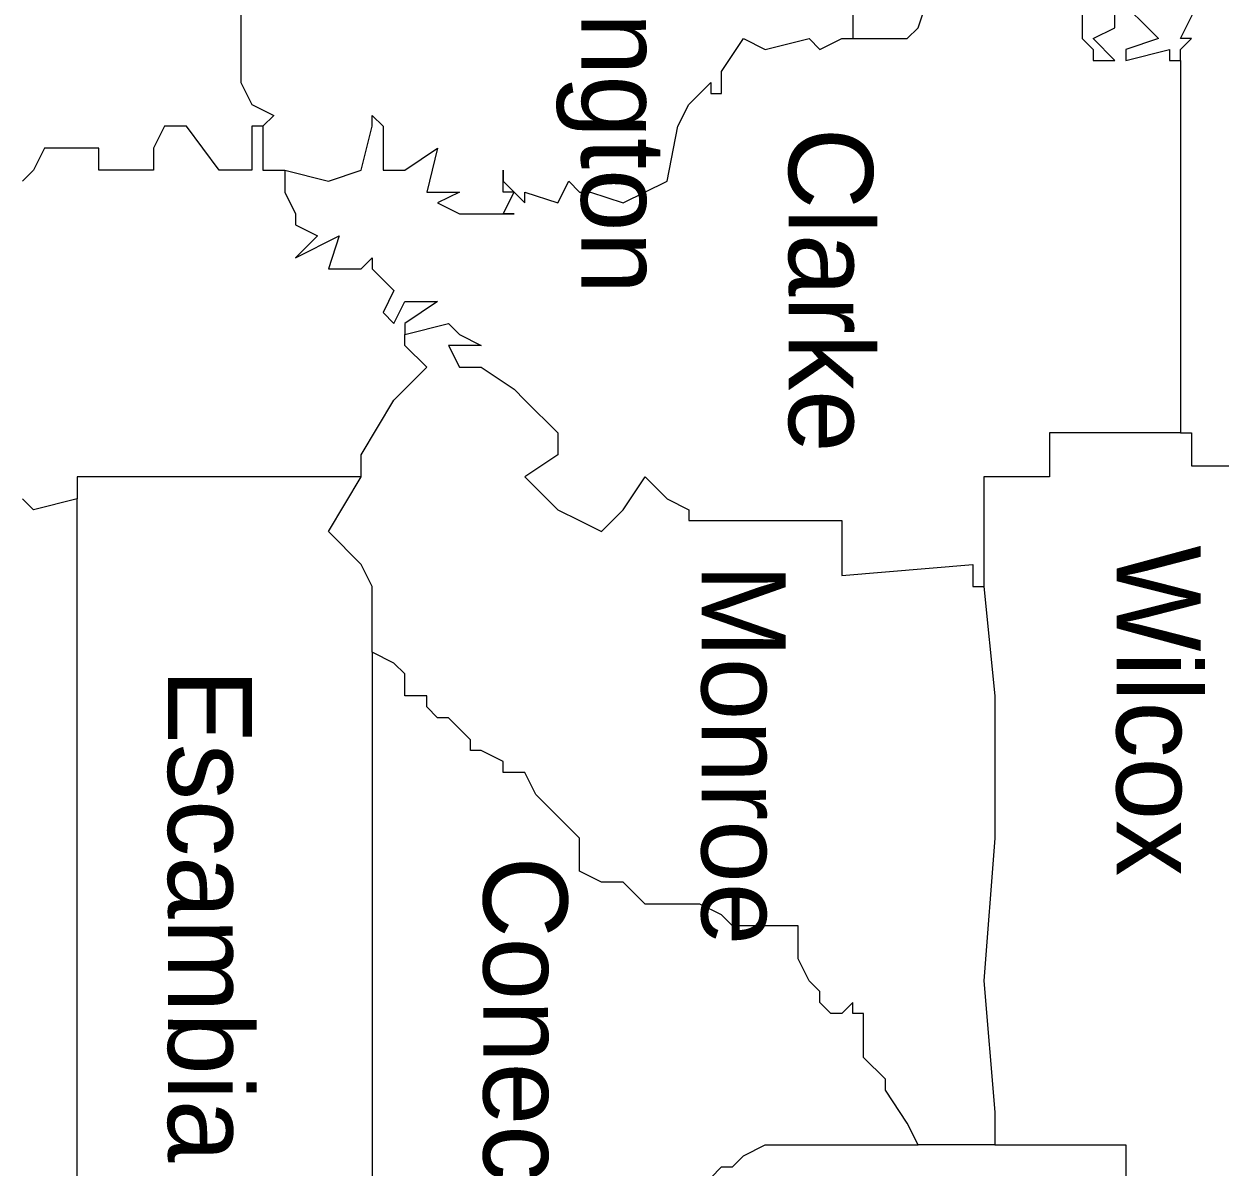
# Model space of a CAD drawing. Extents: x 0 to 0.917, y 0 to 0.708.
# Drawn here: x 0.3538 to 0.4279, y 0.5421 to 0.6129 of the extents above; entities that cross this region are included whole.
import ezdxf

# ---------------------------------------------------------------- set-up
doc = ezdxf.new("R2010")
doc.units = 0
doc.layers.add('ANNO-SHT', color=7, linetype='Continuous')
doc.layers.add('ANNO-TXT', color=7, linetype='Continuous')

msp = doc.modelspace()

# ---------------------------------------------------------------- linework, layer by layer
at = {"layer": 'ANNO-SHT'}
msp.add_line((0.413951, 0.54347), (0.409214, 0.54347), dxfattribs=at)
for points in [[(0.365231, 0.63306), (0.365231, 0.626952), (0.367261, 0.626952), (0.367261, 0.62288), (0.367261, 0.609305), (0.367938, 0.607948), (0.369291, 0.607269), (0.368614, 0.60659), (0.368614, 0.603876), (0.369968, 0.603876)], [(0.365231, 0.63306), (0.365231, 0.626952), (0.367261, 0.626952), (0.367261, 0.62288), (0.367261, 0.609305), (0.367938, 0.607948), (0.369291, 0.607269), (0.368614, 0.60659), (0.368614, 0.603876), (0.369968, 0.603876)], [(0.405154, 0.624916), (0.405154, 0.61202), (0.405831, 0.61202), (0.408537, 0.61202), (0.409214, 0.612699), (0.409891, 0.614735)], [(0.419364, 0.614735), (0.419364, 0.61202), (0.420041, 0.611341), (0.420041, 0.610663), (0.421394, 0.610663), (0.420041, 0.61202), (0.421394, 0.612699), (0.421394, 0.614735)], [(0.421394, 0.614735), (0.424101, 0.61202), (0.422071, 0.611341), (0.422071, 0.610663), (0.424777, 0.611341), (0.424777, 0.610663), (0.425454, 0.610663), (0.425454, 0.611341), (0.426131, 0.61202), (0.425454, 0.61202), (0.426807, 0.614735)], [(0.369968, 0.603876), (0.372674, 0.603197), (0.374704, 0.603876), (0.375381, 0.60659), (0.375381, 0.607269), (0.376058, 0.60659), (0.376058, 0.603876), (0.376734, 0.603876), (0.377411, 0.603876), (0.379441, 0.605233), (0.378764, 0.602518), (0.380794, 0.602518), (0.379441, 0.601839), (0.380794, 0.601161), (0.382148, 0.601161), (0.383501, 0.601161), (0.384178, 0.601161), (0.384178, 0.601161), (0.383501, 0.601161), (0.384178, 0.602518), (0.383501, 0.602518), (0.383501, 0.602518), (0.383501, 0.603876), (0.383501, 0.603197), (0.384178, 0.602518), (0.384854, 0.601839), (0.384854, 0.602518), (0.386884, 0.601839), (0.387561, 0.603197), (0.388238, 0.602518), (0.388914, 0.602518), (0.390944, 0.601839), (0.393651, 0.603197), (0.394328, 0.60659), (0.395004, 0.607948), (0.396358, 0.609305), (0.396358, 0.608627), (0.397034, 0.608627), (0.397034, 0.609984), (0.398388, 0.61202), (0.399741, 0.611341), (0.402448, 0.61202), (0.403124, 0.611341), (0.404478, 0.61202), (0.405154, 0.61202)], [(0.425454, 0.610663), (0.425454, 0.607269), (0.425454, 0.593016), (0.425454, 0.587586), (0.426131, 0.587586), (0.426131, 0.586908), (0.426131, 0.58555), (0.426807, 0.58555), (0.434927, 0.58555), (0.434927, 0.581478), (0.434927, 0.579442), (0.435604, 0.579442), (0.441017, 0.579442), (0.442371, 0.579442), (0.443047, 0.579442), (0.443724, 0.578763), (0.443724, 0.578084), (0.443724, 0.578084), (0.443724, 0.577406), (0.443724, 0.576727), (0.443724, 0.576727)], [(0.368614, 0.60659), (0.367938, 0.60659), (0.367938, 0.605233), (0.367938, 0.603876), (0.367261, 0.603876), (0.365908, 0.603876), (0.363878, 0.60659), (0.363878, 0.60659), (0.362524, 0.60659), (0.361848, 0.605233), (0.361848, 0.603876), (0.361848, 0.603876), (0.360495, 0.603876), (0.359818, 0.603876), (0.359818, 0.603876), (0.359141, 0.603876), (0.358465, 0.603876), (0.358465, 0.605233), (0.358465, 0.605233), (0.357111, 0.605233), (0.355758, 0.605233), (0.355081, 0.605233), (0.355081, 0.605233), (0.355081, 0.605233), (0.354405, 0.603876), (0.354405, 0.603876), (0.353728, 0.603197)], [(0.369968, 0.603876), (0.369968, 0.602518), (0.370644, 0.601161), (0.370644, 0.600482), (0.371998, 0.599803), (0.370644, 0.598446), (0.373351, 0.599803), (0.372674, 0.597767), (0.373351, 0.597767), (0.374704, 0.597767), (0.375381, 0.598446), (0.375381, 0.597767), (0.376734, 0.59641), (0.376058, 0.595052), (0.376734, 0.594374), (0.377411, 0.595731), (0.379441, 0.595731), (0.377411, 0.594374), (0.377411, 0.593695)], [(0.369968, 0.603876), (0.369968, 0.602518), (0.370644, 0.601161), (0.370644, 0.600482), (0.371998, 0.599803), (0.370644, 0.598446), (0.373351, 0.599803), (0.372674, 0.597767), (0.373351, 0.597767), (0.374704, 0.597767), (0.375381, 0.598446), (0.375381, 0.597767), (0.376734, 0.59641), (0.376058, 0.595052), (0.376734, 0.594374), (0.377411, 0.595731), (0.379441, 0.595731), (0.377411, 0.594374), (0.377411, 0.593695)], [(0.377411, 0.593695), (0.380118, 0.594374), (0.380794, 0.593695), (0.382148, 0.593016), (0.380118, 0.593016), (0.380794, 0.591659), (0.382148, 0.591659), (0.384178, 0.590301), (0.384854, 0.589622), (0.384854, 0.589622), (0.386884, 0.587586), (0.386884, 0.586229), (0.384854, 0.584871), (0.386884, 0.582835), (0.386884, 0.582835), (0.388238, 0.582157), (0.389591, 0.581478), (0.390944, 0.582835), (0.392298, 0.584871), (0.393651, 0.583514), (0.395004, 0.582835), (0.395004, 0.582157), (0.396358, 0.582157), (0.404478, 0.582157), (0.404478, 0.578763), (0.412597, 0.579442), (0.412597, 0.578084), (0.413274, 0.578084)], [(0.409214, 0.54347), (0.408537, 0.544827), (0.408537, 0.544827), (0.407184, 0.546863), (0.407184, 0.547542), (0.405831, 0.548899), (0.405831, 0.550257), (0.405831, 0.550936), (0.405831, 0.551614), (0.405831, 0.551614), (0.405154, 0.551614), (0.405154, 0.552293), (0.404478, 0.551614), (0.403801, 0.551614), (0.403801, 0.551614), (0.403124, 0.552293), (0.403124, 0.552972), (0.402448, 0.55365), (0.401771, 0.555008), (0.401771, 0.556365), (0.401771, 0.557044), (0.399741, 0.557044), (0.398388, 0.557044), (0.397711, 0.557044), (0.397034, 0.557723), (0.395681, 0.558401), (0.395004, 0.558401), (0.395004, 0.558401), (0.393651, 0.558401), (0.392298, 0.558401), (0.391621, 0.55908), (0.390944, 0.559759), (0.390944, 0.559759), (0.389591, 0.559759), (0.389591, 0.559759), (0.388238, 0.560438), (0.388238, 0.562474), (0.387561, 0.563152), (0.385531, 0.565189), (0.385531, 0.565189), (0.385531, 0.565189), (0.384854, 0.566546), (0.384178, 0.566546), (0.384178, 0.566546), (0.383501, 0.566546), (0.383501, 0.567225), (0.382148, 0.567904), (0.381471, 0.567904), (0.381471, 0.568582), (0.380118, 0.56994), (0.379441, 0.56994), (0.379441, 0.56994), (0.378764, 0.570618), (0.378764, 0.571297), (0.378764, 0.571297), (0.377411, 0.571297), (0.377411, 0.572655), (0.377411, 0.572655), (0.376734, 0.573333), (0.375381, 0.574012), (0.375381, 0.577406), (0.375381, 0.578084), (0.374704, 0.579442), (0.372674, 0.581478), (0.374704, 0.584871), (0.374704, 0.586229), (0.376734, 0.589622), (0.377411, 0.590301), (0.378764, 0.591659), (0.377411, 0.593016), (0.377411, 0.593695)], [(0.409214, 0.54347), (0.408537, 0.544827), (0.408537, 0.544827), (0.407184, 0.546863), (0.407184, 0.547542), (0.405831, 0.548899), (0.405831, 0.550257), (0.405831, 0.550936), (0.405831, 0.551614), (0.405831, 0.551614), (0.405154, 0.551614), (0.405154, 0.552293), (0.404478, 0.551614), (0.403801, 0.551614), (0.403801, 0.551614), (0.403124, 0.552293), (0.403124, 0.552972), (0.402448, 0.55365), (0.401771, 0.555008), (0.401771, 0.556365), (0.401771, 0.557044), (0.399741, 0.557044), (0.398388, 0.557044), (0.397711, 0.557044), (0.397034, 0.557723), (0.395681, 0.558401), (0.395004, 0.558401), (0.395004, 0.558401), (0.393651, 0.558401), (0.392298, 0.558401), (0.391621, 0.55908), (0.390944, 0.559759), (0.390944, 0.559759), (0.389591, 0.559759), (0.389591, 0.559759), (0.388238, 0.560438), (0.388238, 0.562474), (0.387561, 0.563152), (0.385531, 0.565189), (0.385531, 0.565189), (0.385531, 0.565189), (0.384854, 0.566546), (0.384178, 0.566546), (0.384178, 0.566546), (0.383501, 0.566546), (0.383501, 0.567225), (0.382148, 0.567904), (0.381471, 0.567904), (0.381471, 0.568582), (0.380118, 0.56994), (0.379441, 0.56994), (0.379441, 0.56994), (0.378764, 0.570618), (0.378764, 0.571297), (0.378764, 0.571297), (0.377411, 0.571297), (0.377411, 0.572655), (0.377411, 0.572655), (0.376734, 0.573333), (0.375381, 0.574012), (0.375381, 0.577406), (0.375381, 0.578084), (0.374704, 0.579442), (0.372674, 0.581478), (0.374704, 0.584871), (0.374704, 0.586229), (0.376734, 0.589622), (0.377411, 0.590301), (0.378764, 0.591659), (0.377411, 0.593016), (0.377411, 0.593695)], [(0.425454, 0.587586), (0.424101, 0.587586), (0.417334, 0.587586), (0.417334, 0.586229), (0.417334, 0.584871), (0.413274, 0.584871), (0.413274, 0.578084), (0.413951, 0.571297), (0.413951, 0.562474), (0.413274, 0.55365), (0.413951, 0.545506), (0.413951, 0.54347)], [(0.374704, 0.584871), (0.360495, 0.584871), (0.357111, 0.584871), (0.357111, 0.584871), (0.357111, 0.583514)], [(0.357111, 0.529895), (0.357111, 0.530574), (0.357111, 0.53261), (0.357111, 0.550936), (0.357111, 0.563831), (0.357111, 0.577406), (0.357111, 0.583514), (0.354405, 0.582835), (0.353728, 0.583514)], [(0.375381, 0.574012), (0.375381, 0.561795), (0.375381, 0.559759), (0.375381, 0.550936), (0.375381, 0.535325)], [(0.393651, 0.530574), (0.393651, 0.53261), (0.393651, 0.533968), (0.393651, 0.540076), (0.394328, 0.540076), (0.394328, 0.540755), (0.395004, 0.540755), (0.395681, 0.541434), (0.396358, 0.541434), (0.397034, 0.542112), (0.397711, 0.542112), (0.398388, 0.542791), (0.399741, 0.54347), (0.400418, 0.54347), (0.403801, 0.54347), (0.404478, 0.54347), (0.409214, 0.54347)], [(0.393651, 0.530574), (0.393651, 0.53261), (0.393651, 0.533968), (0.393651, 0.540076), (0.394328, 0.540076), (0.394328, 0.540755), (0.395004, 0.540755), (0.395681, 0.541434), (0.396358, 0.541434), (0.397034, 0.542112), (0.397711, 0.542112), (0.398388, 0.542791), (0.399741, 0.54347), (0.400418, 0.54347), (0.403801, 0.54347), (0.404478, 0.54347), (0.409214, 0.54347)], [(0.413951, 0.54347), (0.409214, 0.54347)], [(0.413951, 0.54347), (0.413951, 0.54347), (0.422071, 0.54347), (0.422071, 0.540755)], [(0.413951, 0.54347), (0.413951, 0.54347), (0.422071, 0.54347), (0.422071, 0.540755)]]:
    msp.add_lwpolyline(points, dxfattribs=at)

# ---------------------------------------------------------------- texts
at = {"layer": 'ANNO-TXT'}
for s, p in [('Washington', (0.388341, 0.632973)), ('Clarke', (0.401196, 0.606502)), ('Wilcox', (0.421498, 0.580624)), ('Monroe', (0.395791, 0.57946)), ('Escambia', (0.36274, 0.572974)), ('Conecuh', (0.382276, 0.561347))]:
    msp.add_text(s, height=0.0052083, rotation=270, dxfattribs=at).set_placement(p)

doc.saveas('drawing.dxf')
